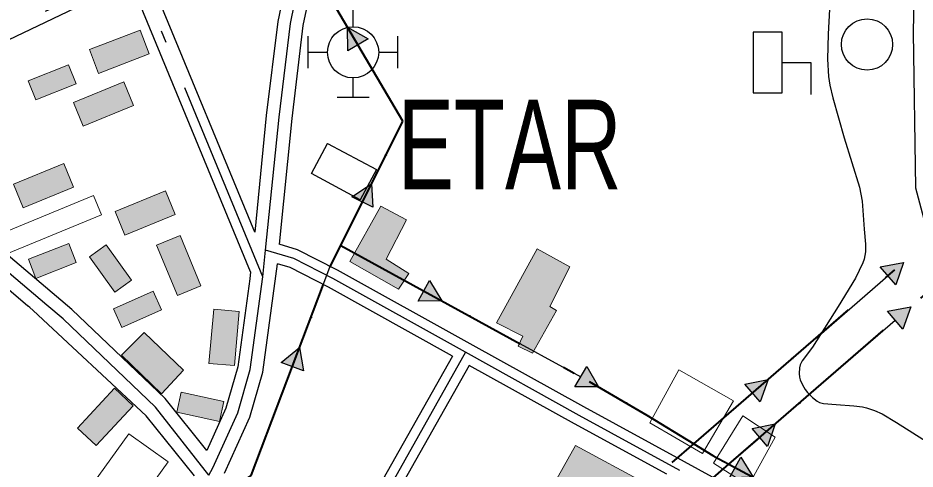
# Model space of a CAD drawing. Extents: x -64005 to -55000, y -89025 to -80000.
# Drawn here: x -62552 to -61851, y -83061 to -82708 of the extents above; entities that cross this region are included whole.
import ezdxf
from ezdxf.enums import TextEntityAlignment as Align

# ---------------------------------------------------------------- set-up
doc = ezdxf.new("R2010")
doc.units = 0
doc.header["$LTSCALE"] = 32
doc.linetypes.add('DOT_DASHED', pattern=[7.7, 5, -1.2, 0.3, -1.2])
doc.linetypes.add('LONG_DASHED', pattern=[7.5, 6, -1.5])
for name, color, linetype, lineweight in [('10', 7, 'Continuous', 25), ('11', 7, 'Continuous', 25), ('16', 7, 'Continuous', 25), ('18', 7, 'Continuous', 25), ('21', 7, 'Continuous', 25), ('3', 7, 'Continuous', 25), ('39', 7, 'LONG_DASHED', 25), ('6', 7, 'Continuous', 25), ('7', 7, 'Continuous', 13), ('8', 7, 'Continuous', 25)]:
    doc.layers.add(name, color=color, linetype=linetype, lineweight=lineweight)

msp = doc.modelspace()

# ---------------------------------------------------------------- hatches: boundary and pattern name
at = {"layer": '18'}
for points in [[(-62294.2, -82733.62), (-62294.34, -82715.12), (-62278.25, -82724.25)], [(-62291.03, -82847.84), (-62275.6, -82837.63), (-62274.47, -82856.09)], [(-61877.99, -82902.66), (-61859.82, -82899.17), (-61865.88, -82916.65)], [(-62230.33, -82913.3), (-62220.73, -82929.11), (-62239.22, -82929.53)], [(-61872.3, -82937.42), (-61854.13, -82933.93), (-61860.19, -82951.41)], [(-62346.12, -82977.38), (-62331.81, -82965.65), (-62328.81, -82983.91)], [(-62107.24, -82980.52), (-62098.06, -82996.58), (-62116.56, -82996.5)], [(-61983.85, -82994.28), (-61965.68, -82990.79), (-61971.74, -83008.27)], [(-61978.16, -83029.04), (-61959.99, -83025.55), (-61966.05, -83043.03)], [(-61986.98, -83051.47), (-61977.22, -83067.18), (-61995.71, -83067.78)]]:
    msp.add_hatch(color=256, dxfattribs=at).paths.add_polyline_path(points)
at = {"layer": '7'}
for points in [[(-62456.47, -82717.51), (-62496.13, -82732.78), (-62488.95, -82751.45), (-62449.29, -82736.18)], [(-62512.37, -82744.53), (-62543.96, -82757.1), (-62538.05, -82771.97), (-62506.46, -82759.4)], [(-62469.26, -82758.08), (-62508.59, -82774.17), (-62501.02, -82792.68), (-62461.69, -82776.59)], [(-62516.11, -82821.81), (-62555.44, -82837.9), (-62547.87, -82856.41), (-62508.54, -82840.32)], [(-62436.71, -82843.3), (-62476.04, -82859.39), (-62468.47, -82877.9), (-62429.14, -82861.81)], [(-62268.2, -82855.22), (-62292.47, -82898.48), (-62254.54, -82920.1), (-62246.39, -82907.96), (-62264.22, -82896.77), (-62248.29, -82865.84)], [(-62443.59, -82885.77), (-62427.38, -82925.06), (-62408.89, -82917.43), (-62425.1, -82878.14)], [(-62512.11, -82884.45), (-62543.81, -82896.74), (-62538.03, -82911.65), (-62506.33, -82899.36)], [(-62463.23, -82913.18), (-62482.92, -82885.46), (-62495.97, -82894.72), (-62476.28, -82922.44)], [(-62149.88, -82970.17), (-62131.11, -82936.78), (-62136.23, -82933.75), (-62120.5, -82902.63), (-62146.1, -82888.6), (-62177.95, -82946.46), (-62157.28, -82956.89), (-62161.07, -82964.67)], [(-62446.25, -82921.7), (-62477.31, -82935.54), (-62470.79, -82950.16), (-62439.74, -82936.31)], [(-62382.82, -82979.92), (-62378.98, -82937.59), (-62398.9, -82935.78), (-62402.74, -82978.11)], [(-62439.69, -83002.08), (-62422.47, -82983.52), (-62453.33, -82953.98), (-62471.13, -82971.78)], [(-62490.84, -83042.36), (-62461.87, -83011.26), (-62476.5, -82997.62), (-62505.47, -83028.72)], [(-62391.07, -83007.99), (-62424.26, -83000.63), (-62427.73, -83016.25), (-62394.54, -83023.61)], [(-62075.32, -83100.97), (-62131.84, -83070.24), (-62116.29, -83042.35), (-62061.11, -83072.13)]]:
    msp.add_hatch(color=256, dxfattribs=at).paths.add_polyline_path(points)

# ---------------------------------------------------------------- linework, layer by layer
at = {"layer": '10'}
msp.add_circle((-61888.28, -82728.74), 20, dxfattribs=at)
at = {"layer": '11'}
msp.add_lwpolyline([(-61954.67, -82742.78), (-61954.67, -82719.03), (-61977.17, -82719.03), (-61977.17, -82766.53), (-61954.67, -82766.53), (-61954.67, -82742.78), (-61932.17, -82742.78), (-61932.17, -82767.78)], dxfattribs=at)
at = {"layer": '16'}
for p, q in [((-62290.01, -82714.85), (-62290.01, -82699.85)), ((-62325.01, -82747.35), (-62325.01, -82722.35)), ((-62255.01, -82747.35), (-62255.01, -82722.35)), ((-62325.01, -82734.85), (-62310.01, -82734.85)), ((-62270.01, -82734.85), (-62255.01, -82734.85)), ((-62290.01, -82769.85), (-62290.01, -82754.85)), ((-62302.51, -82769.85), (-62277.51, -82769.85))]:
    msp.add_line(p, q, dxfattribs=at)
msp.add_lwpolyline([(-62284.57, -82850.14), (-62322.42, -82829.61), (-62309.9, -82806.08), (-62271.6, -82826.57)], close=True, dxfattribs=at)
msp.add_circle((-62290.01, -82734.85), 20, dxfattribs=at)
at = {"layer": '18'}
for p, q in [((-62299.66, -82885.87), (-62234.78, -82921.42)), ((-61927.88, -82958.07), (-61871.94, -82909.66)), ((-61922.19, -82992.83), (-61866.25, -82944.42)), ((-62176.88, -82953.14), (-62112, -82988.68)), ((-62363.57, -83049.86), (-62337.46, -82980.64))]:
    msp.add_line(p, q, dxfattribs=at)
at = {"layer": '18', "linetype": 'DOT_DASHED', "lineweight": 40}
for points in [[(-62477.87, -83403.87), (-62367.98, -83378.64), (-62216.73, -83247.74), (-62089.34, -83137.49), (-61996.3, -83056.97), (-61098.84, -82280.26), (-60868.7, -82080.1), (-60312.19, -81596.09), (-60219.71, -81521.05), (-59047.52, -80569.92), (-58561.43, -80162.65), (-58367.89, -80000.48)], [(-62504.64, -83341.78), (-62247.39, -83226.15), (-62239.3, -83222.48), (-62226.91, -83216.87), (-62023.78, -83041.07), (-61118.5, -82257.6), (-60888.39, -82057.46), (-60331.49, -81573.12), (-59784.07, -81124.16), (-59559.17, -80826.16), (-59559.05, -80755.05), (-59556.19, -80635.98), (-59694.59, -80228.4), (-59810.95, -80144.91), (-59929.04, -80078.55)], [(-62504.29, -83399.68), (-62504.64, -83341.78), (-62504.98, -83286.19), (-62522.71, -83234.36), (-62468.31, -83132.29), (-62369.58, -83065.81), (-62308.12, -82902.84), (-62299.66, -82885.87), (-62251.17, -82788.64), (-62343.25, -82631.81)], [(-62299.66, -82885.87), (-62105.54, -82992.22), (-62060.34, -83018.57), (-62023.78, -83041.07), (-62008.9, -83050.23), (-62004.05, -83052.82), (-61996.3, -83056.97), (-61876.09, -83121.31), (-61916.59, -83198.87), (-61966.66, -83292.39)]]:
    msp.add_lwpolyline(points, dxfattribs=at)
at = {"layer": '18'}
for points in [[(-62294.2, -82733.62), (-62294.34, -82715.12), (-62278.25, -82724.25)], [(-62291.03, -82847.84), (-62275.6, -82837.63), (-62274.47, -82856.09)], [(-61877.99, -82902.66), (-61859.82, -82899.17), (-61865.88, -82916.65)], [(-62230.33, -82913.3), (-62220.73, -82929.11), (-62239.22, -82929.53)], [(-61872.3, -82937.42), (-61854.13, -82933.93), (-61860.19, -82951.41)], [(-62346.12, -82977.38), (-62331.81, -82965.65), (-62328.81, -82983.91)], [(-62107.24, -82980.52), (-62098.06, -82996.58), (-62116.56, -82996.5)], [(-61983.85, -82994.28), (-61965.68, -82990.79), (-61971.74, -83008.27)], [(-61978.16, -83029.04), (-61959.99, -83025.55), (-61966.05, -83043.03)], [(-61986.98, -83051.47), (-61977.22, -83067.18), (-61995.71, -83067.78)]]:
    msp.add_lwpolyline(points, close=True, dxfattribs=at)
for points in [[(-62253.29, -82792.89), (-62251.17, -82788.64), (-62286.22, -82728.94)], [(-62314.17, -82918.87), (-62308.12, -82902.84), (-62299.66, -82885.87), (-62282.75, -82851.97)], [(-62033.74, -83049.69), (-62023.78, -83041.07), (-61977.8, -83001.27)], [(-62054.94, -83021.89), (-62023.78, -83041.07), (-62008.9, -83050.23), (-62004.05, -83052.82), (-61996.3, -83056.97), (-61991.34, -83059.62)], [(-62028.05, -83084.45), (-61996.3, -83056.97), (-61972.11, -83036.03)]]:
    msp.add_lwpolyline(points, dxfattribs=at)
for centre in [(-62264.45, -82815.26), (-62322.99, -82942.26), (-62198.8, -82941.12), (-61946.78, -82974.43), (-62076.46, -83009.17), (-61941.09, -83009.19)]:
    msp.add_circle(centre, 0.5, dxfattribs=at)
at = {"layer": '21'}
for p, q in [((-62366.92, -82875.42), (-62452.41, -82667.91)), ((-62370.27, -82906.66), (-62463.38, -82680.66))]:
    msp.add_line(p, q, dxfattribs=at)
for points in [[(-62692.7, -82788.68), (-62495.63, -82694.5), (-62463.38, -82680.66)], [(-62198.43, -82962.94), (-62302.28, -82905.26), (-62333.42, -82889.27), (-62347.77, -82884.9)], [(-62212.31, -82972.39), (-62309.34, -82918.5), (-62339.08, -82903.23), (-62349.06, -82900.19)], [(-62031.04, -83055.24), (-62109.66, -83012.24), (-62198.43, -82962.94)], [(-62212.31, -82972.39), (-62286.02, -83103.21), (-62314.81, -83155.18)], [(-62199.19, -82979.68), (-62272.92, -83110.53), (-62304.52, -83167.56)], [(-62044.75, -83064.84), (-62116.9, -83025.38), (-62199.19, -82979.68)], [(-62028.71, -83465.34), (-61983.32, -83385.31), (-61915, -83261.83), (-61873.49, -83186.28), (-61868.82, -83171.31), (-61868.82, -83155.24), (-61876.42, -83140.05), (-61935.24, -83107.66), (-62031.04, -83055.24)]]:
    msp.add_lwpolyline(points, dxfattribs=at)
at = {"layer": '3', "lineweight": 13}
msp.add_lwpolyline([(-62284.57, -82850.14), (-62322.42, -82829.61), (-62309.9, -82806.08), (-62271.6, -82826.57)], close=True, dxfattribs=at)
at = {"layer": '39', "linetype": 'DOT_DASHED'}
msp.add_line((-62360.55, -82910.57), (-62459.34, -82670.77), dxfattribs=at)
at = {"layer": '39', "linetype": 'Continuous'}
for p, q in [((-62360.55, -82910.57), (-62358.42, -82889.5)), ((-62402.67, -83065.49), (-62399.51, -83059.78))]:
    msp.add_line(p, q, dxfattribs=at)
at = {"layer": '39', "linetype": 'DOT_DASHED'}
for points in [[(-62709.42, -82788.36), (-62498.73, -82687.67), (-62459.34, -82670.77)], [(-62202.07, -82969.5), (-62305.81, -82911.88), (-62336.25, -82896.25), (-62358.42, -82889.5)], [(-62202.07, -82969.5), (-62279.47, -83106.87), (-62314.87, -83170.76)], [(-62034.64, -83061.82), (-62113.28, -83018.81), (-62202.07, -82969.5)]]:
    msp.add_lwpolyline(points, dxfattribs=at)
at = {"layer": '39', "linetype": 'Continuous'}
for points in [[(-62358.42, -82889.5), (-62347.88, -82785.49), (-62339.05, -82712.38), (-62332.29, -82680.06)], [(-62402.67, -83065.49), (-62444.39, -83012.47), (-62516.67, -82943.4), (-62529.32, -82932.71), (-62573.01, -82895.8), (-62590.33, -82882.11)], [(-62399.51, -83059.78), (-62380.01, -83016.72), (-62370.37, -82982.99), (-62360.55, -82910.57)]]:
    msp.add_lwpolyline(points, dxfattribs=at)
at = {"layer": '6'}
for points in [[(-62254.61, -82499.69), (-62256.61, -82505.54), (-62282.38, -82569.99), (-62307.16, -82633.94), (-62322.14, -82680.4), (-62329.17, -82714.01), (-62337.94, -82786.58), (-62347.77, -82884.9)], [(-62342.6, -82680.53), (-62348.93, -82710.75), (-62357.82, -82784.39), (-62366.92, -82875.42)], [(-62404.34, -83046.19), (-62437.01, -83005.69), (-62509.97, -82935.96), (-62566.68, -82888.06), (-62677.94, -82800.14), (-62692.7, -82788.68)], [(-62413.9, -83066.19), (-62451.76, -83019.25), (-62540.12, -82936.68), (-62542.72, -82934.48), (-62543.85, -82933.52), (-62544.14, -82933.28), (-62579.34, -82903.54), (-62588.82, -82896.04), (-62588.84, -82895.95)], [(-62390.48, -83064.08), (-62370.6, -83020.17), (-62360.56, -82985.05), (-62349.06, -82900.19)], [(-62370.27, -82906.66), (-62370.83, -82911.91), (-62380.18, -82980.93), (-62389.42, -83013.26), (-62404.34, -83046.19)]]:
    msp.add_lwpolyline(points, dxfattribs=at)
at = {"layer": '7', "lineweight": 25}
msp.add_lwpolyline([(-61916.55, -82681.39), (-61918.73, -82720.65), (-61919.08, -82740.28), (-61918.33, -82753.77), (-61917.36, -82760.48), (-61915.14, -82770.43), (-61906.12, -82801.7), (-61894.29, -82840.3), (-61892.16, -82851.18), (-61890.63, -82873.26), (-61889.58, -82884.97), (-61889.56, -82890.82), (-61890.5, -82896.61), (-61891.47, -82899.46), (-61897.31, -82911.48), (-61910.92, -82933.56), (-61930.93, -82965.39), (-61939.1, -82976.11), (-61940.54, -82979.35), (-61941.08, -82981.56), (-61941.35, -82985.97), (-61941, -82988.99), (-61940.49, -82990.99), (-61938.82, -82994.98), (-61936.59, -82998.68), (-61934.93, -83000.86), (-61930.93, -83004.84), (-61927.27, -83007.67), (-61925.33, -83008.74), (-61922.2, -83009.63), (-61912.34, -83010.19), (-61898.61, -83011.24), (-61891.77, -83012.16), (-61888.6, -83012.85), (-61882.45, -83014.89), (-61876.53, -83017.63), (-61865.28, -83024.27), (-61821.89, -83051.88)], dxfattribs=at)
at = {"layer": '7'}
for points in [[(-62456.47, -82717.51), (-62496.13, -82732.78), (-62488.95, -82751.45), (-62449.29, -82736.18)], [(-62512.37, -82744.53), (-62543.96, -82757.1), (-62538.05, -82771.97), (-62506.46, -82759.4)], [(-62469.26, -82758.08), (-62508.59, -82774.17), (-62501.02, -82792.68), (-62461.69, -82776.59)], [(-62516.11, -82821.81), (-62555.44, -82837.9), (-62547.87, -82856.41), (-62508.54, -82840.32)], [(-62492.94, -82846.93), (-62566.8, -82877.37), (-62560.57, -82892.51), (-62486.71, -82862.07)], [(-62436.71, -82843.3), (-62476.04, -82859.39), (-62468.47, -82877.9), (-62429.14, -82861.81)], [(-62268.2, -82855.22), (-62292.47, -82898.48), (-62254.54, -82920.1), (-62246.39, -82907.96), (-62264.22, -82896.77), (-62248.29, -82865.84)], [(-62443.59, -82885.77), (-62427.38, -82925.06), (-62408.89, -82917.43), (-62425.1, -82878.14)], [(-62512.11, -82884.45), (-62543.81, -82896.74), (-62538.03, -82911.65), (-62506.33, -82899.36)], [(-62463.23, -82913.18), (-62482.92, -82885.46), (-62495.97, -82894.72), (-62476.28, -82922.44)], [(-62149.88, -82970.17), (-62131.11, -82936.78), (-62136.23, -82933.75), (-62120.5, -82902.63), (-62146.1, -82888.6), (-62177.95, -82946.46), (-62157.28, -82956.89), (-62161.07, -82964.67)], [(-62446.25, -82921.7), (-62477.31, -82935.54), (-62470.79, -82950.16), (-62439.74, -82936.31)], [(-62382.82, -82979.92), (-62378.98, -82937.59), (-62398.9, -82935.78), (-62402.74, -82978.11)], [(-62439.69, -83002.08), (-62422.47, -82983.52), (-62453.33, -82953.98), (-62471.13, -82971.78)], [(-62035.35, -82983.26), (-61992.64, -83007.42), (-62016.95, -83048.51), (-62058.1, -83024.52)], [(-62490.84, -83042.36), (-62461.87, -83011.26), (-62476.5, -82997.62), (-62505.47, -83028.72)], [(-62391.07, -83007.99), (-62424.26, -83000.63), (-62427.73, -83016.25), (-62394.54, -83023.61)], [(-61985.43, -83019.24), (-61960.05, -83035.9), (-61981.06, -83073.66), (-62008.17, -83056.31)], [(-62465.27, -83033.12), (-62498.1, -83078.87), (-62467.42, -83100.89), (-62434.59, -83055.14)], [(-62075.32, -83100.97), (-62131.84, -83070.24), (-62116.29, -83042.35), (-62061.11, -83072.13)]]:
    msp.add_lwpolyline(points, close=True, dxfattribs=at)
at = {"layer": '8', "linetype": 'LONG_DASHED'}
msp.add_lwpolyline([(-61492.61, -82145.55), (-61650.28, -82234.27), (-61785.38, -82343.46), (-61830, -82395.25), (-61839.58, -82419.77), (-61846.7, -82437.95), (-61850.2, -82549.69), (-61852.12, -82719.25), (-61850.39, -82840.81), (-61832.81, -82907.62), (-61787.86, -83037.39)], dxfattribs=at)

# ---------------------------------------------------------------- texts
at = {"layer": '6', "width": 0.7}
msp.add_text('ETAR', height=70, rotation=0.007, dxfattribs=at).set_placement((-62167.57, -82841.99), align=Align.CENTER)

doc.saveas('drawing.dxf')
